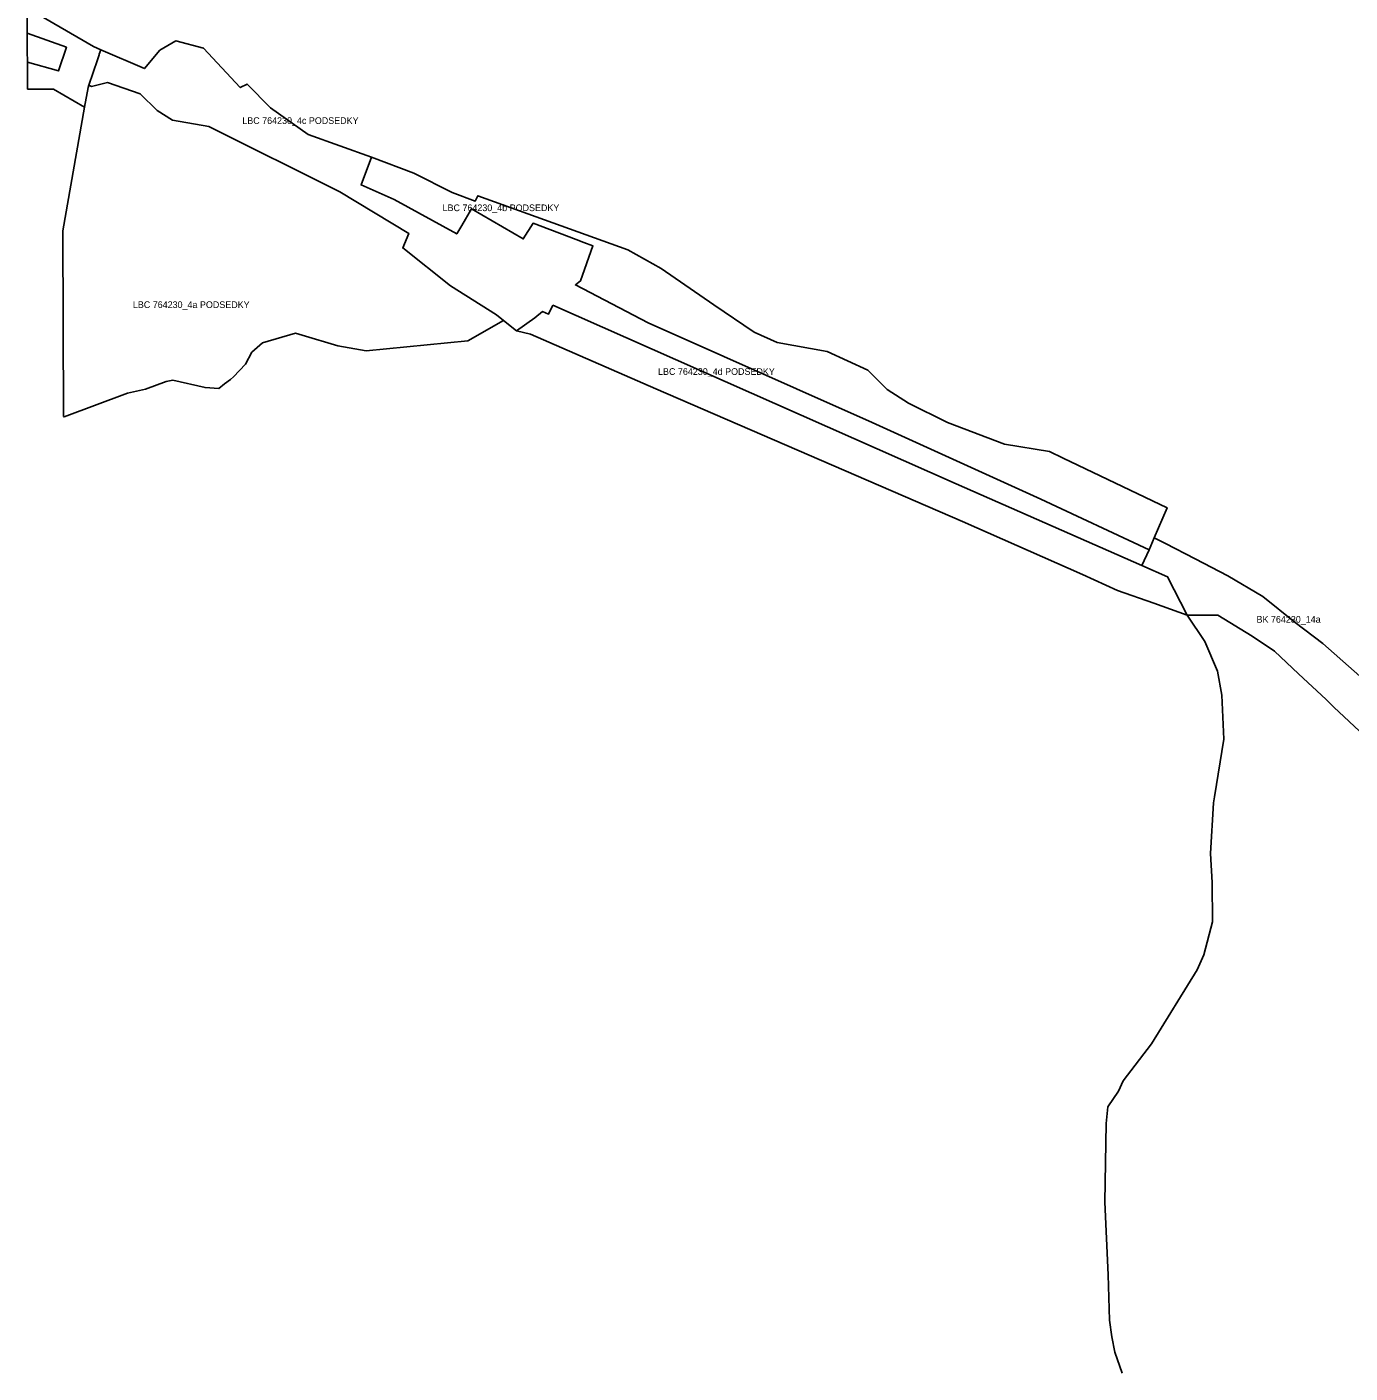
# Model space of a CAD drawing. Extents: x -521616 to -516782, y -1190061 to -1184927.
# Drawn here: x -520689 to -519897, y -1187423 to -1186617 of the extents above; entities that cross this region are included whole.
import ezdxf

# ---------------------------------------------------------------- set-up
doc = ezdxf.new("R2010")
doc.units = 0
for name, color, linetype in [('i_prvek_l_s', 7, 'Continuous'), ('LBC_n', 7, 'Continuous'), ('LBC_s', 7, 'Continuous'), ('LBK_n', 7, 'Continuous'), ('LBK_s', 7, 'Continuous')]:
    doc.layers.add(name, color=color, linetype=linetype)

msp = doc.modelspace()

# ---------------------------------------------------------------- linework, layer by layer
at = {"layer": 'i_prvek_l_s'}
msp.add_lwpolyline([(-520033.69, -1187423.22), (-520038.01, -1187410.61), (-520039.71, -1187401.51), (-520041.1, -1187391.48), (-520042.02, -1187364.47), (-520044.03, -1187320.95), (-520043.26, -1187273.88), (-520042.21, -1187263.91), (-520035.73, -1187254.49), (-520032.92, -1187248.3), (-520016.12, -1187226.09), (-519988.78, -1187181.79), (-519984.81, -1187172.8), (-519979.48, -1187153.12), (-519979.69, -1187129.59), (-519980.67, -1187112.17), (-519978.95, -1187081.91), (-519978.24, -1187078.36), (-519972.76, -1187043.74), (-519973.95, -1187017.39), (-519976.57, -1187003.02), (-519984.11, -1186985.31), (-519994.79, -1186969.47)], dxfattribs=at)
at = {"layer": 'LBC_n'}
msp.add_line((-520652.23, -1186652.29), (-520652.23, -1186652.29), dxfattribs=at)
for points in [[(-520667.43, -1186850.56), (-520667.77, -1186739.45), (-520654.76, -1186665.44), (-520652.69, -1186653.64), (-520652.23, -1186652.29), (-520650.62, -1186653.07), (-520640.95, -1186650.79), (-520621.44, -1186657.47), (-520611.25, -1186667.48), (-520602.11, -1186673.29), (-520580.31, -1186676.98), (-520501.91, -1186716.18), (-520460.61, -1186741.14), (-520464.3, -1186749.75), (-520435.64, -1186772.42), (-520408.22, -1186789.83), (-520403.98, -1186793.19), (-520425.37, -1186805.43), (-520486.24, -1186811.23), (-520503.13, -1186808.37), (-520524.46, -1186801.99), (-520528.59, -1186800.75), (-520548.33, -1186806.55), (-520554.65, -1186812.18), (-520558.38, -1186819.28), (-520565.56, -1186826.82), (-520567.47, -1186828.46), (-520570.94, -1186831.16), (-520574.48, -1186833.92), (-520582.62, -1186833.31), (-520601.93, -1186828.98), (-520605.83, -1186829.59), (-520618.21, -1186834.35), (-520629.12, -1186836.6), (-520667.05, -1186850.8)], [(-520309.58, -1186762.07), (-520278.05, -1186783.78), (-520253.85, -1186800.06), (-520240.06, -1186806.37), (-520210.14, -1186811.65), (-520185.94, -1186822.94), (-520174.35, -1186834.38), (-520161.44, -1186842.74), (-520138.12, -1186854.18), (-520104.09, -1186867.24), (-520077.1, -1186871.64), (-520068.84, -1186875.58), (-520006.7, -1186905.23), (-520014.43, -1186923.24), (-520017.5, -1186930.4), (-520082.33, -1186900.21), (-520183.23, -1186854.16), (-520317.35, -1186794.57), (-520360.88, -1186771.86), (-520357.92, -1186769.46), (-520350.41, -1186748.53), (-520355.9, -1186746.45), (-520360.44, -1186744.73), (-520386.26, -1186734.94), (-520392.11, -1186744.31), (-520423.06, -1186726.34), (-520429.01, -1186736.33), (-520432, -1186741.36), (-520469.5, -1186720.72), (-520489.22, -1186712.06), (-520483.02, -1186695.4), (-520457.68, -1186705.03), (-520434.66, -1186716.59), (-520420.95, -1186721.79), (-520419.44, -1186718.51), (-520329.53, -1186750.78)], [(-520374.47, -1186784.03), (-520241.59, -1186842.91), (-520132.95, -1186890.9), (-520021.92, -1186939.78), (-520006.39, -1186946.62), (-519994.79, -1186969.47), (-520014.58, -1186962.43), (-520036.32, -1186954.86), (-520057.44, -1186945.19), (-520129.23, -1186913.42), (-520220.95, -1186873.71), (-520312.71, -1186833.98), (-520387.78, -1186801.36), (-520396.27, -1186799.32), (-520385.2, -1186791.58), (-520380.62, -1186787.87), (-520380.62, -1186787.87), (-520377.11, -1186789.47)]]:
    msp.add_lwpolyline(points, close=True, dxfattribs=at)
at = {"layer": 'LBC_s'}
for p, q in [((-520652.23, -1186652.29), (-520652.23, -1186652.29)), ((-520360.88, -1186771.86), (-520360.88, -1186771.86))]:
    msp.add_line(p, q, dxfattribs=at)
for points in [[(-520374.47, -1186784.03), (-520377.11, -1186789.47), (-520380.62, -1186787.87), (-520380.62, -1186787.87), (-520385.2, -1186791.58), (-520396.27, -1186799.32), (-520403.98, -1186793.19), (-520408.22, -1186789.83), (-520435.64, -1186772.42), (-520464.3, -1186749.75), (-520460.61, -1186741.14), (-520501.91, -1186716.18), (-520580.31, -1186676.98), (-520602.11, -1186673.29), (-520611.25, -1186667.48), (-520621.44, -1186657.47), (-520640.95, -1186650.79), (-520650.62, -1186653.07), (-520652.23, -1186652.29), (-520652.23, -1186652.29), (-520647.1, -1186637.19), (-520646.07, -1186634.15), (-520645.95, -1186633.79), (-520645.06, -1186631.17), (-520618.94, -1186642.42), (-520609.7, -1186631.42), (-520600.14, -1186625.68), (-520583.56, -1186630.14), (-520561.57, -1186653.73), (-520557.34, -1186651.7), (-520543.45, -1186665.79), (-520520.94, -1186681.91), (-520483.02, -1186695.4), (-520489.22, -1186712.06), (-520469.5, -1186720.72), (-520432, -1186741.36), (-520429.01, -1186736.33), (-520423.06, -1186726.34), (-520392.11, -1186744.31), (-520386.26, -1186734.94), (-520360.44, -1186744.73), (-520355.9, -1186746.45), (-520350.41, -1186748.53), (-520357.92, -1186769.46), (-520360.88, -1186771.86)], [(-520360.88, -1186771.86), (-520317.35, -1186794.57), (-520183.23, -1186854.16), (-520082.33, -1186900.21), (-520017.5, -1186930.4), (-520021.92, -1186939.78), (-520132.95, -1186890.9), (-520241.59, -1186842.91)], [(-520241.59, -1186842.91), (-520374.47, -1186784.03)]]:
    msp.add_lwpolyline(points, dxfattribs=at)
at = {"layer": 'LBK_n'}
msp.add_lwpolyline([(-520689.28, -1186605.97), (-520649.52, -1186629.25), (-520645.06, -1186631.17), (-520645.95, -1186633.79), (-520646.07, -1186634.15), (-520647.1, -1186637.19), (-520652.23, -1186652.29), (-520652.69, -1186653.64), (-520654.76, -1186665.44), (-520673.46, -1186654.64), (-520688.88, -1186654.64), (-520688.91, -1186650.76), (-520688.94, -1186646.62), (-520688.97, -1186642.4), (-520688.98, -1186640.76), (-520688.99, -1186638.57), (-520670.45, -1186643.73), (-520665.66, -1186629.65), (-520689.13, -1186621.21), (-520689.15, -1186617.42), (-520689.18, -1186613.67)], close=True, dxfattribs=at)
at = {"layer": 'LBK_s'}
msp.add_lwpolyline([(-520689.04, -1186631.79), (-520689.1, -1186624.61), (-520689.11, -1186623.07), (-520689.13, -1186621.21), (-520665.66, -1186629.65), (-520670.45, -1186643.73), (-520688.99, -1186638.57)], close=True, dxfattribs=at)
for points in [[(-519994.79, -1186969.47), (-520006.39, -1186946.62), (-520021.92, -1186939.78), (-520017.5, -1186930.4)], [(-520017.5, -1186930.4), (-520014.43, -1186923.24), (-520007.61, -1186926.56), (-519989.93, -1186935.79)], [(-519989.93, -1186935.79), (-519970.36, -1186945.95), (-519949.41, -1186958.4), (-519930.08, -1186973.99), (-519913.58, -1186986.44), (-519863.94, -1187030.15), (-519867.23, -1187034.17), (-519876.04, -1187044.95), (-519880.01, -1187049.8), (-519882.31, -1187047.61), (-519906.86, -1187024.54), (-519911.57, -1187020.11), (-519928.06, -1187004.61), (-519942.46, -1186991.09), (-519955.81, -1186982.07), (-519976.25, -1186969.59), (-519994.79, -1186969.47)]]:
    msp.add_lwpolyline(points, dxfattribs=at)

# ---------------------------------------------------------------- texts
at = {"layer": 'LBC_n'}
for s, p in [('LBC 764230_4b PODSEDKY', (-520440.44, -1186727.71)), ('LBC 764230_4a PODSEDKY', (-520625.85, -1186785.7)), ('LBC 764230_4d PODSEDKY', (-520311.45, -1186825.72))]:
    msp.add_text(s, height=4, dxfattribs=at).set_placement(p)
at = {"layer": 'LBC_s'}
msp.add_text('LBC 764230_4c PODSEDKY', height=4, dxfattribs=at).set_placement((-520560.34, -1186675.52))
at = {"layer": 'LBK_s'}
msp.add_text('BK 764230_14a', height=4, dxfattribs=at).set_placement((-519953.16, -1186974.06))

doc.saveas('drawing.dxf')
